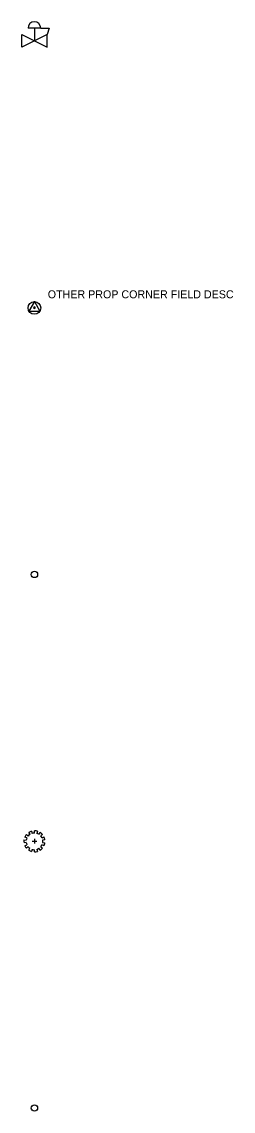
# Model space of a CAD drawing. Extents: x 98 to 2902, y -6 to 903.
# Drawn here: x 1697.6 to 1737.3, y 449.4 to 653.6 of the extents above; entities that cross this region are included whole.
import ezdxf

# ---------------------------------------------------------------- set-up
doc = ezdxf.new("R2010")
doc.units = 0
for name, color, linetype in [('V-SITE-OTLN', 7, 'Continuous'), ('V-SITE-VEGE', 7, 'Continuous'), ('V-SURV-DATA', 7, 'Continuous'), ('V-WATR-VALT', 7, 'Continuous')]:
    doc.layers.add(name, color=color, linetype=linetype)

msp = doc.modelspace()

# ---------------------------------------------------------------- linework, layer by layer
at = {"layer": 'V-SITE-OTLN'}
for centre in [(1700, 550), (1700, 450)]:
    msp.add_circle(centre, 0.595, dxfattribs=at)
at = {"layer": 'V-SITE-VEGE'}
for p, q in [((1698.03, 500.25), (1698.46, 500.18)), ((1698.58, 500.61), (1698.19, 500.78)), ((1698.49, 501.26), (1698.81, 500.98)), ((1699.17, 501.3), (1698.93, 501.65)), ((1699.46, 501.89), (1699.56, 501.47)), ((1700, 501.53), (1700.01, 501.96)), ((1700, 500.42), (1700, 499.58)), ((1700.57, 501.88), (1700.45, 501.47)), ((1700.84, 501.29), (1701.08, 501.64)), ((1701.51, 501.27), (1701.19, 500.99)), ((1701.42, 500.62), (1701.8, 500.82)), ((1701.97, 500.25), (1701.54, 500.19)), ((1698.46, 499.76), (1698.04, 499.69)), ((1698.19, 499.16), (1698.58, 499.35)), ((1698.83, 498.96), (1698.5, 498.68)), ((1698.94, 498.3), (1699.15, 498.68)), ((1699.58, 498.48), (1699.46, 498.07)), ((1699.58, 500), (1700.42, 500)), ((1700, 497.99), (1700, 498.42)), ((1700.43, 498.49), (1700.56, 498.08)), ((1701.08, 498.31), (1700.85, 498.68)), ((1701.17, 498.95), (1701.5, 498.68)), ((1701.81, 499.15), (1701.41, 499.31)), ((1701.54, 499.75), (1701.97, 499.7))]:
    msp.add_line(p, q, dxfattribs=at)
for radius, start, end in [(1.98, 172.27, 188.583), (1.98, 139.7777, 156.0738), (1.56, 156.0557, 172.7558), (1.56, 122.254, 140.086), (1.98, 105.972, 122.5562), (1.56, 89.9461, 106.3473), (1.98, 73.2952, 89.5718), (1.56, 57.451, 73.0843), (1.98, 40.7122, 57.1166), (1.56, 24.4529, 40.4774), (1.98, 7.9671, 24.8625), (1.98, 204.5394, 220.9852), (1.56, 188.0619, 204.0332), (1.56, 221.2062, 236.7795), (1.98, 237.6108, 254.1981), (1.56, 254.31, 270.043), (1.56, 285.9559, 303.0564), (1.98, 302.8434, 319.0222), (1.56, 318.6432, 334.5795), (1.56, 351.5431, 7.6203), (1.98, 335.3123, 351.7042), (1.98, 270.0356, 286.342)]:
    msp.add_arc((1700, 499.98), radius, start, end, dxfattribs=at)
at = {"layer": 'V-SURV-DATA'}
for p, q in [((1700, 601.14), (1698.97, 599.35)), ((1700, 601.14), (1701.03, 599.35)), ((1698.97, 599.35), (1701.03, 599.35))]:
    msp.add_line(p, q, dxfattribs=at)
msp.add_circle((1700, 599.95), 1.19, dxfattribs=at)
msp.add_arc((1700, 600), 0.165, 92.2877, 90.5674, dxfattribs=at)
at = {"layer": 'V-WATR-VALT'}
msp.add_line((1700, 652.38), (1700, 650), dxfattribs=at)
for points in [[(1701.19, 652.38), (1698.81, 652.38)], [(1701.19, 652.38), (1702.78, 652.38), (1702.38, 651.19)]]:
    msp.add_lwpolyline(points, dxfattribs=at)
msp.add_lwpolyline([(1697.62, 648.81), (1697.62, 651.19), (1702.38, 648.81), (1702.38, 651.19)], close=True, dxfattribs=at)
msp.add_arc((1700, 652.38), 1.19, 0, 180, dxfattribs=at)

# ---------------------------------------------------------------- texts
at = {"layer": 'V-SURV-DATA'}
msp.add_text('OTHER PROP CORNER FIELD DESC', height=1.5, dxfattribs=at).set_placement((1702.5, 601.75))

doc.saveas('drawing.dxf')
